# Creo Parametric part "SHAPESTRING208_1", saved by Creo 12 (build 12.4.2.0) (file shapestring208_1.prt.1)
Units: Custom; MM, KILOGRAM, SECS

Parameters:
  PTC_WM_ITERATION = "0"
  PTC_WM_VERSION = "-.0"
  PTC_WM_LIFECYCLE_STATE = "In Work"
  PTC_WM_LIFECYCLE = "MO_CADDocument"
  PTC_WM_CREATED_BY = "Maximilian Roepper (Z0017RMS: MO)"
  PTC_WM_CREATED_ON = "18-Sep-26 11:36:42 AM"
  PTC_WM_MODIFIED_BY = "Maximilian Roepper (Z0017RMS: MO)"
  PTC_WM_MODIFIED_ON = "18-Sep-26 11:36:46 AM"
  PDMLINKNUMBER = "PDM000071455317"
  PTC_WM_NAME = "shapestring208_1.prt"
  PTC_WM_NUMBER = "PDM000071455317"

Other parameters: WEIGHT, WEIGHT_FACTOR, WEIGHT_ADD, _MASS_TEMP, _DIFF_TEMP, MC_ERRORS, SUPPLIER

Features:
  1. coordinate system
  2. datum plane "PRT_YZ"
  3. datum plane "PRT_XY"
  4. datum plane "PRT_XZ"
  5. coordinate system
  6. datum axis
  7. datum axis
  8. datum axis
  9. coordinate system
  10. imported feature

Other named items: PRT, SIEMENS_MO, DRW_VIEW_ORG, PRT_X, PRT_Y, PRT_Z, CS0, ROUGH_GROB

Layers: 00_STD_CSYS-KSYS, 01_STD_PLANES-EBENEN, 02_STD_AXES-ACHSEN, 03_STD_CSYS-KSYS, 24_IMPORT_FEAT-IMPORT_KE, INTFCLR

Surfaces: 1 plane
